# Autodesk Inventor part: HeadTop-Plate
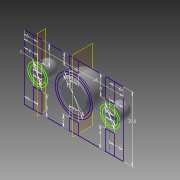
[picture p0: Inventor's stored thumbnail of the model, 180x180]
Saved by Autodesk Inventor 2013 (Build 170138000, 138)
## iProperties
Created: 2013-04
Part Number: HeadTop-Plate
Material: Generic
Document SubType Name: Modeling
Designer: frankenteddy
Density: 1 g/cm^3
Author: frankenteddy
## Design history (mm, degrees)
sketch "Sketch1"
  geometry: L1 (-22.5, 14.75)-(22.5, 14.75); L2 (22.5, 14.75)-(22.5, -14.75); L3 (22.5, -14.75)-(-22.5, -14.75); L4 (-22.5, -14.75)-(-22.5, 14.75); L5 (-18.5, 14.75)-(-14.5, 14.75); L6 (-14.5, 14.75)-(-14.5, 5.75); L7 (-14.5, 5.75)-(-18.5, 5.75); L8 (-18.5, 5.75)-(-18.5, 14.75); L9 (-2, 14.75)-(2, 14.75); L10 (2, 14.75)-(2, 9.75); L11 (2, 9.75)-(-2, 9.75); L12 (-2, 9.75)-(-2, 14.75); L13 (14.5, 14.75)-(18.5, 14.75); L14 (18.5, 14.75)-(18.5, 5.75); L15 (18.5, 5.75)-(14.5, 5.75); L16 (14.5, 5.75)-(14.5, 14.75); L17 (-18.5, -14.75)-(-14.5, -14.75); L18 (-14.5, -14.75)-(-14.5, -5.75); L19 (-14.5, -5.75)-(-18.5, -5.75); L20 (-18.5, -5.75)-(-18.5, -14.75); L21 (-2, -14.75)-(2, -14.75); L22 (2, -14.75)-(2, -9.75); L23 (2, -9.75)-(-2, -9.75); L24 (-2, -9.75)-(-2, -14.75); L25 (14.5, -14.75)-(18.5, -14.75); L26 (18.5, -14.75)-(18.5, -5.75); L27 (18.5, -5.75)-(14.5, -5.75); L28 (14.5, -5.75)-(14.5, -14.75); L29 (-16.5, 5.75)-(-16.5, 14.75); L30 (0, 9.75)-(0, 14.75); L31 (16.5, 5.75)-(16.5, 14.75); L32 (16.5, -5.75)-(16.5, -14.75); L33 (0, -9.75)-(0, -14.75); L34 (-16.5, -5.75)-(-16.5, -14.75); L35 (-22.5, 0)-(22.5, 0); L36 (0, 14.75)-(0, -14.75); C1 r 7.5 at (0, 0); C2 r 3.5 at (16.5, 0); C3 r 3.5 at (-16.5, 0); C4 r 4.5 at (-16.5, 0); C5 r 8.5 at (0, 0); C6 r 4.5 at (16.5, 0); 4 further points
  constraints: 72 end point, 16 midpoint, 14 parallel, 9 perpendicular, 7 coincident, 7 horizontal, 6 centre point, 6 point on line, 2 collinear, 1 horizontal alignment, 1 vertical alignment
  dimensions: "d0" = 45 distance of L1.start L1.end; "d2" = 29.5 distance of L3.end L1.start; "d3" = 15 diameter of C1; "d4" = 7 diameter of C2; "d5" = 7 diameter of C3; "d6" = 6 distance from line of C3.centre L4; "d7" = 6 distance from line of C2.centre L2; "d8" = 4 distance of L6.end L7.end; "d9" = 4 distance of L10.end L11.end; "d10" = 4 distance of L14.end L15.end; "d11" = 4 distance of L19.end L18.end; "d12" = 4 distance of L23.end L22.end; "d13" = 4 distance of L27.end L26.end; "d14" = 6 distance between parallel lines of L4 L29; "d15" = 6 distance between parallel lines of L4 L34; "d16" = 6 distance between parallel lines of L2 L32; "d17" = 6 distance between parallel lines of L2 L31; "d18" = 9 distance of L5.end L6.end; "d19" = 9 distance of L17.end L18.end; "d20" = 5 distance of L9.end L10.end; "d21" = 5 distance of L21.end L22.end; "d22" = 9 distance of L15.end L13.start; "d23" = 9 distance of L27.end L25.start; "d40" = 9 diameter of C4; "d41" = 17 diameter of C5; "d42" = 9 diameter of C6
workplane "Work Plane1"
sketch "Sketch2"
  geometry: L1 (0, 0)-(1.62, 0) reference; L2 (1.62, 0)-(1.62, -29.5) reference; L3 (1.62, -29.5)-(0, -29.5); L4 (0, -29.5)-(0, 0); L5 (1.62, -14.75)-(0, -14.75); L6 (1.62, -14.75)-(4.62, -14.75); L7 (4.62, -14.75)-(4.62, -11.25); L8 (4.62, -11.25)-(1.62, -11.25); L9 (1.62, -11.25)-(1.62, -14.75); L10 (8.12, -14.75)-(1.12, -14.75); A1 r 3.5 centre (4.62, -14.75) between (8.12, -14.75) and (1.12, -14.75)
  constraints: 20 end point, 4 parallel, 3 horizontal, 2 perpendicular, 2 point on circle, 2 point on line, 1 centre point, 1 coincident, 1 midpoint, 1 vertical
  dimensions: "d28" = 1.62 distance of L2.end L3.end; "d29" = 29.5 distance of L1.end L2.end; "d30" = 3 distance of L8.end L7.end; "d31" = 3.5 distance of L7.end L6.end; "d32" = 7 diameter of A1
revolve "Revolution1" sketch "Sketch2" stored, may be unused: angle "d33" = 90 deg
workplane "Work Plane2"
sketch "Sketch3"
  geometry: L1 (0, 0)-(1.62, 0) reference; L2 (1.62, 0)-(1.62, -29.5) reference; L3 (1.62, -29.5)-(0, -29.5); L4 (0, -29.5)-(0, 0); L5 (1.62, -14.75)-(0, -14.75); L6 (1.62, -14.75)-(4.62, -14.75); L7 (4.62, -14.75)-(4.62, -7.25); L8 (4.62, -7.25)-(1.62, -7.25); L9 (1.62, -7.25)-(1.62, -14.75); L10 (12.12, -14.75)-(0, -14.75); L11 (0, -14.75)-(0, -20.658); A1 r 7.5 centre (4.62, -14.75) between (0, -20.658) and (0, -8.842)
  constraints: 22 end point, 4 parallel, 3 horizontal, 3 perpendicular, 3 point on circle, 2 midpoint, 2 point on line, 1 centre point, 1 coincident, 1 collinear, 1 vertical
  dimensions: "d34" = 1.62 distance of L2.end L3.end; "d35" = 29.5 distance of L1.end L2.end; "d36" = 3 distance of L8.end L7.end; "d37" = 7.5 distance of L7.end L6.end; "d38" = 15 diameter of A1
revolve "Revolution2" sketch "Sketch3" stored, may be unused: angle "d39" = 90 deg
mirror "Mirror1"
body "Solid1"
